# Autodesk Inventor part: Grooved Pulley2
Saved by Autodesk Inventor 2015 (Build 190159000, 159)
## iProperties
Created: 2015-03
Part Number: Grooved Pulley2
Material: Steel
Document SubType Name: Modeling
Designer: Uglješa
Density: 1 g/cm^3
Appearance: Steel
CustomPartVersion: 1
Author: Uglješa
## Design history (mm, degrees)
sketch "Main Sketch"
  geometry: L1 (0, 76)-(42, 76); L2 (42, 76)-(42, 12.861); L3 (42, 12.861)-(31, 9.498); L4 (31, 9.498)-(31, 6.502); L5 (31, 6.502)-(42, 3.139); L6 (42, 3.139)-(42, 0); L7 (42, 0)-(0, 0); L8 (40, 12.25)-(40, 3.75); L9 (31, 8)-(40, 8); L10 (42, 12.861)-(42, 3.139); L11 (0, -4)-(0, 24) reference; L12 (0, 0)-(0, 76)
  constraints: 22 end point, 5 perpendicular, 2 collinear, 2 midpoint, 2 point on line, 1 parallel
  dimensions: "d0" = 8.5 distance of L8.start L8.end (= da_Bw); "d1" = 34 deg angle of L3 L5 (= da_Alfa); "d2" = 2 distance between parallel lines of L2 L8 (= da_c); "d6" = 76 distance between parallel lines of L7 L1 (computed from d5, da_ng, da_Sg); "d21" = 80 diameter of L8 L11 (= da_Dw); "d25" = 11 distance between parallel lines of L4 L10 (= da_Hd); "d27" = 8 distance between parallel lines of L7 L9 (= da_Se)
node "Belt Plane"
revolve "Body" stored, may be unused: angle "d7" = 90 deg
revolve "Groove" stored, may be unused: angle "d15" = 90 deg
fillet "Fillet External" dims "d8" = 0 (computed from da_r1), "d10" = 0, "da_r1" = 0 [user parameter; used in 1 equation term]
fillet "Fillet Internal" dims "d9" = 0 (computed from da_r2), "d11" = 0, "da_r2" = 0 [user parameter; used in 1 equation term]
pattern_linear "Groove Pattern" dims "d18" = 12 (= da_Sg)
node "Keyway1"
body "Solid1"
feature "Hub Keyway"
other parameters: "d5" = 8 (= da_Se), "da_Bw" = 8.5 [user parameter; used in 1 equation term], "da_Alfa" = 34 deg [user parameter; used in 1 equation term], "da_c" = 2 [user parameter; used in 1 equation term], "da_Dw" = 80 [user parameter; used in 1 equation term], "da_Hd" = 11 [user parameter; used in 1 equation term], "da_Se" = 8 [user parameter; used in 2 equation terms], "da_Sg" = 12 [user parameter; used in 2 equation terms], "d24" = 0, "d26" = 0
